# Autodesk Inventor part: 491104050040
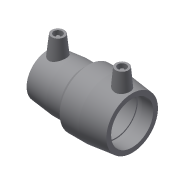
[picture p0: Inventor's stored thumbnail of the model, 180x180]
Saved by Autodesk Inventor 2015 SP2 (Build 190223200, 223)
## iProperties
Created: 2017-06
Part Number: 491104050040
Material: Generic
Description: PLASSON REDUCING COUPLER 50-40
Document SubType Name: Modeling
Designer: KIM
Mass: 54.8237 g
Surface Area: 155.252 cm^2
Volume: 54.8237 cm^3
Density: 1 g/cm^3
Appearance: Default
Author: KIM
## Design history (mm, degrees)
derived "491104.ipt"
feature "Solid1::491104.ipt"
tag "TaggingFeature1"
body "Solid1"
other parameters: "L_2" = 44, "D_1" = 56, "A_1" = 48, "d_2" = 12, "L_1" = 49, "A_" = 52, "D_" = 68, "d2" = 56, "d3" = 44, "d4" = 26.4, "d5" = 50.4, "d8" = 168 deg, "d10" = 17.6, "d11" = 5.86667, "d14" = 17.6296, "d15" = 44, "d19" = 2.2, "d20" = 168 deg, "d22" = 108.92847, "d25" = 135 deg, "d29" = 48, "d30" = 15, "d31" = 38, "d34" = 6 deg, "d35" = 15, "d38" = 26, "d39" = 5 deg, "d41" = 4, "d42" = 14, "d43" = 0, "d45" = 4, "d46" = 14, "d47" = 0, "d48" = 56, "d50" = 68, "d52" = 36, "d53" = 19.6, "d54" = 6.53333, "d55" = 168 deg, "d56" = 29.4, "d57" = 49, "d58" = 61.2, "d59" = 2.2, "d60" = 135 deg, "d61" = 52, "d62" = 15, "d64" = 4, "d66" = 5 deg, "d67" = 14, "d68" = 0, "d69" = 38, "d70" = 56, "d71" = 68, "d73" = 63.92, "d76" = 2.2, "d77" = 168 deg, "d79" = 2.2, "d80" = 49, "d81" = 36, "d82" = 52.64, "d83" = 120 deg, "d88" = 15, "d89" = 24.5, "d90" = 5 deg, "d92" = 4, "d93" = 14, "d94" = 0, "d95" = 3, "d96" = 0, "d97" = 3, "d98" = 0, "d99" = 12.76, "d100" = 3.19, "d101" = 51.0608, "d102" = 20 deg, "d103" = 14.21, "d104" = 3.5525, "d105" = 62.0024, "d106" = 3.60705, "d107" = 3, "d108" = 0, "d109" = 3, "d110" = 0
